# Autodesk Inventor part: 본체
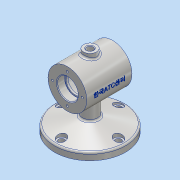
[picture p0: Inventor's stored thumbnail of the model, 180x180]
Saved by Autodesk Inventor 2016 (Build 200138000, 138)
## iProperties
Created: 2018-12
Part Number: 본체
Material: 알루미늄 6061
Document SubType Name: Modeling
Designer: 3sil_cad018
Density: 2.7 g/cm^3
Appearance: 알루미늄 - 평지
Mass: 685.082 g
Surface Area: 555.459 cm^2
Volume: 253.734 cm^3
Author: 3sil_cad018
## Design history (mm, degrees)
sketch "스케치2"
  geometry: L1 (0, 0)-(-55, 0); L2 (-55, 0)-(-55, 11); L3 (-55, 11)-(0, 11); L4 (0, 11)-(0, 0); L5 (-55, 11)-(0, 25.737); L6 (0, 25.737)-(0, 11)
  constraints: 12 end point, 2 parallel, 1 horizontal, 1 perpendicular, 1 vertical
  dimensions: "d0" = 11 distance of L1.end L2.end; "d1" = 75 deg angle of L5 L2; "d2" = 110 diameter of L2 L4
revolve "회전1" sketch "스케치2" stored, may be unused: angle "d3" = 90 deg
node "작업 평면1"
sketch "스케치3" dims "d5" = 88
  geometry: 3 further points
  constraints: 2 horizontal alignment, 1 coincident, 2 other
hole "구멍1" sketch "스케치3" at (44, 0) diameter "d6" = 9; stored, may be unused: countersink angle "d10" = 90 deg, drill point angle "d12" = 118 deg; dims "d7" = 6, "d8" = 14, "d9" = 10, "d11" = 8
sketch "스케치4"
  geometry: L1 (0, 75)-(-35, 75); L2 (-35, 75)-(-35, 105); L3 (-35, 105)-(0, 105); L4 (0, 105)-(0, 75); L5 (55, 0)-(-55, 0) reference; L6 (-35, 91)-(-23, 91); L7 (-23, 91)-(-23, 89); L8 (-23, 89)-(-20, 89); L9 (-20, 89)-(-20, 100); L10 (-20, 100)-(0, 100); L11 (0, 75)-(35, 75); L12 (35, 75)-(35, 105); L13 (35, 105)-(0, 105); L14 (35, 91)-(23, 91); L15 (23, 91)-(23, 89); L16 (23, 89)-(20, 89); L17 (20, 89)-(20, 100); L18 (20, 100)-(0, 100); 1 further point
  constraints: 34 end point, 7 symmetric about line, 5 perpendicular, 4 point on line, 2 horizontal, 2 parallel
  dimensions: "d16" = 75 distance from line of L1.start L5; "d17" = 60 diameter of L3 L1; "d18" = 35 distance between parallel lines of L4 L2; "d19" = 32 diameter of L6 L1; "d20" = 28 diameter of L8 L1; "d21" = 50 diameter of L10 L1; "d22" = 20 distance from line of L4 L9.end; "d23" = 12 distance of L6.start L6.end
revolve "회전2" stored, may be unused: angle "d24" = 90 deg
node "작업 평면2"
sketch "스케치5"
  geometry: C1 r 10 at (0, 0); 1 further point
  constraints: 1 centre point, 1 coincident
  dimensions: "d26" = 20 diameter of C1
extrude "돌출1" join sketch "스케치5" stored distance "d27" = 10; taper "d28" = 0 deg
sketch "스케치6"
  geometry: C1 r 12 at (0, 0); 1 further point
  constraints: 1 centre point, 1 coincident
  dimensions: "d29" = 24 diameter of C1
extrude "돌출2" join sketch "스케치6" stored distance "d30" = 10; taper "d31" = 0 deg
fillet "모깎기1" dims "d32" = 3
revolve "회전3" stored, may be unused: angle "d33" = 90 deg
fillet "모깎기2" dims "d38" = 3
fillet "모깎기3" dims "d39" = 0.3
chamfer "모따기1" distance "d40" = 1; stored, may be unused: second distance "d41" = 2, angle "d42" = 45 deg
sketch "스케치7" dims "d43" = 46
  geometry: 4 further points
  constraints: 2 vertical alignment, 1 coincident, 2 other
hole "구멍2" sketch "스케치7" at (0, 23) diameter "d44" = 3.242; stored, may be unused: countersink angle "d48" = 90 deg, drill point angle "d50" = 118 deg; dims "d45" = 8, "d46" = 14, "d47" = 10, "d49" = 10
hole "구멍3" diameter "d56" = 10; stored, may be unused: countersink angle "d60" = 90 deg, drill point angle "d62" = 118 deg; dims "d54" = 10, "d55" = 10, "d57" = 8, "d58" = 14, "d59" = 10, "d61" = 10
chamfer "모따기2" distance "d63" = 1; stored, may be unused: second distance "d64" = 2, angle "d65" = 45 deg
node "작업 평면3"
sketch "스케치8"
  geometry: L1 (-35, 45)-(-35, 105) reference; 2 further points
  constraints: 1 other
  dimensions: "d67" = 35 distance from line of point (0, 75) L1; "d68" = 30 vertical distance of L1.end point (0, 75)
feature "엠보싱1" sketch "스케치8" dims "d0" = 11, "d1" = 75 deg, "d2" = 110, "d16" = 75, "d17" = 60, "d18" = 35, "d19" = 32, "d20" = 28, "d21" = 50, "d22" = 20, "d23" = 12, "d69" = 0.5, "d70" = 0
node "솔리드1"
pattern_circular "원형 패턴1" dims angle "d14" = 360 deg
pattern_circular "원형 패턴2" dims angle "d52" = 360 deg
mirror "대칭1"
other parameters: "d25" = -112, "d34" = 0.5, "d35" = 2, "d36" = 0
